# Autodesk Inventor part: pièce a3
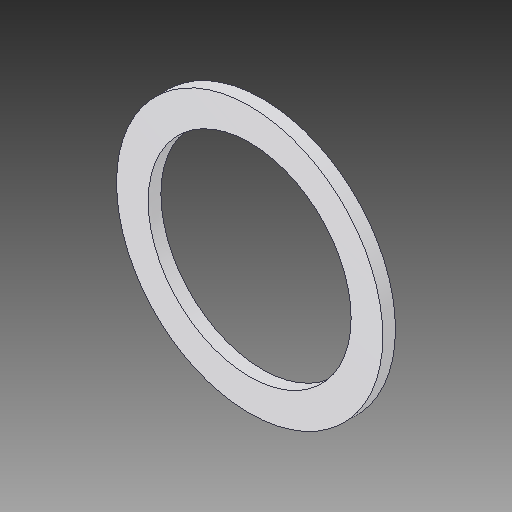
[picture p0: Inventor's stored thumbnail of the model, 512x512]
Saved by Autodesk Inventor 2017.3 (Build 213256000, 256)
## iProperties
Created: 2007-12
Part Number: pièce a3
Material: solidworks materials|Alliage 7079|22
Document SubType Name: Modeling
Designer: ficho
Appearance: 227,227,233
Author: ficho
Sending System: SolidWorks 2009
Last Author: christophe
Last Saved: 2011-01-23
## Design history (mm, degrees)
extrude "Extrusion1"
node "Solide1"
